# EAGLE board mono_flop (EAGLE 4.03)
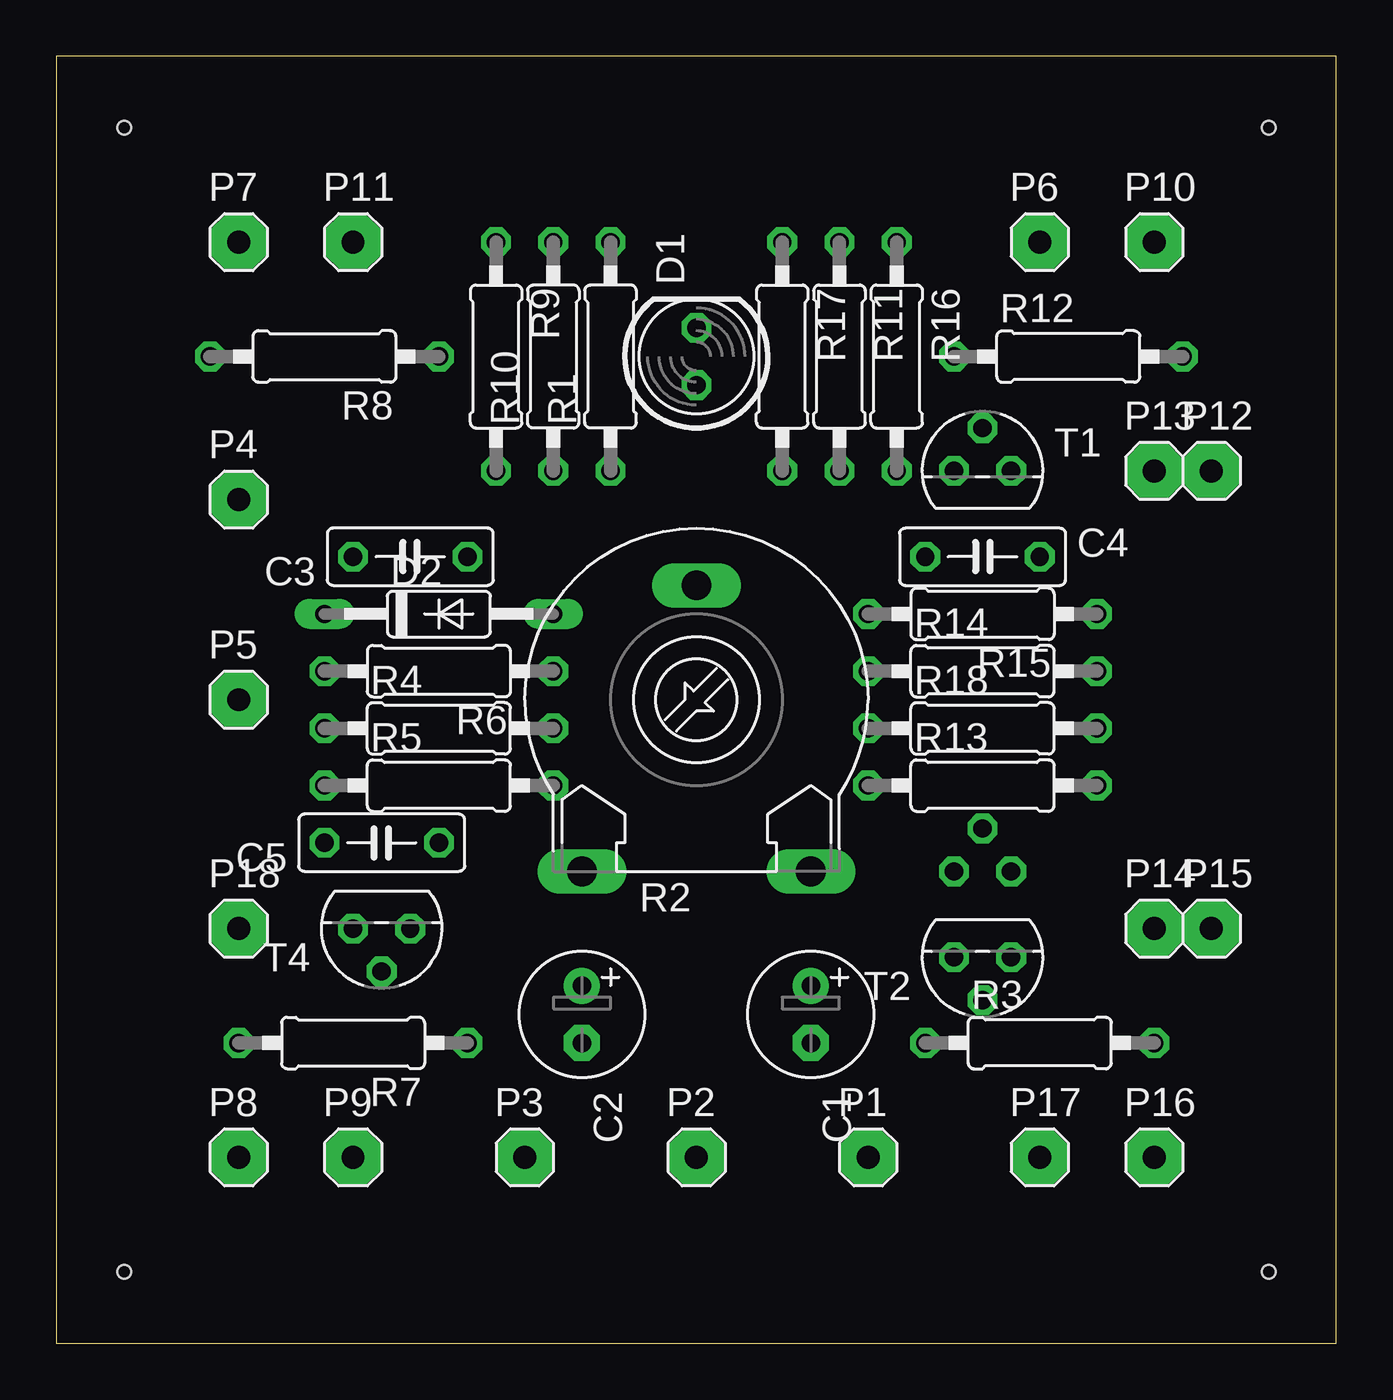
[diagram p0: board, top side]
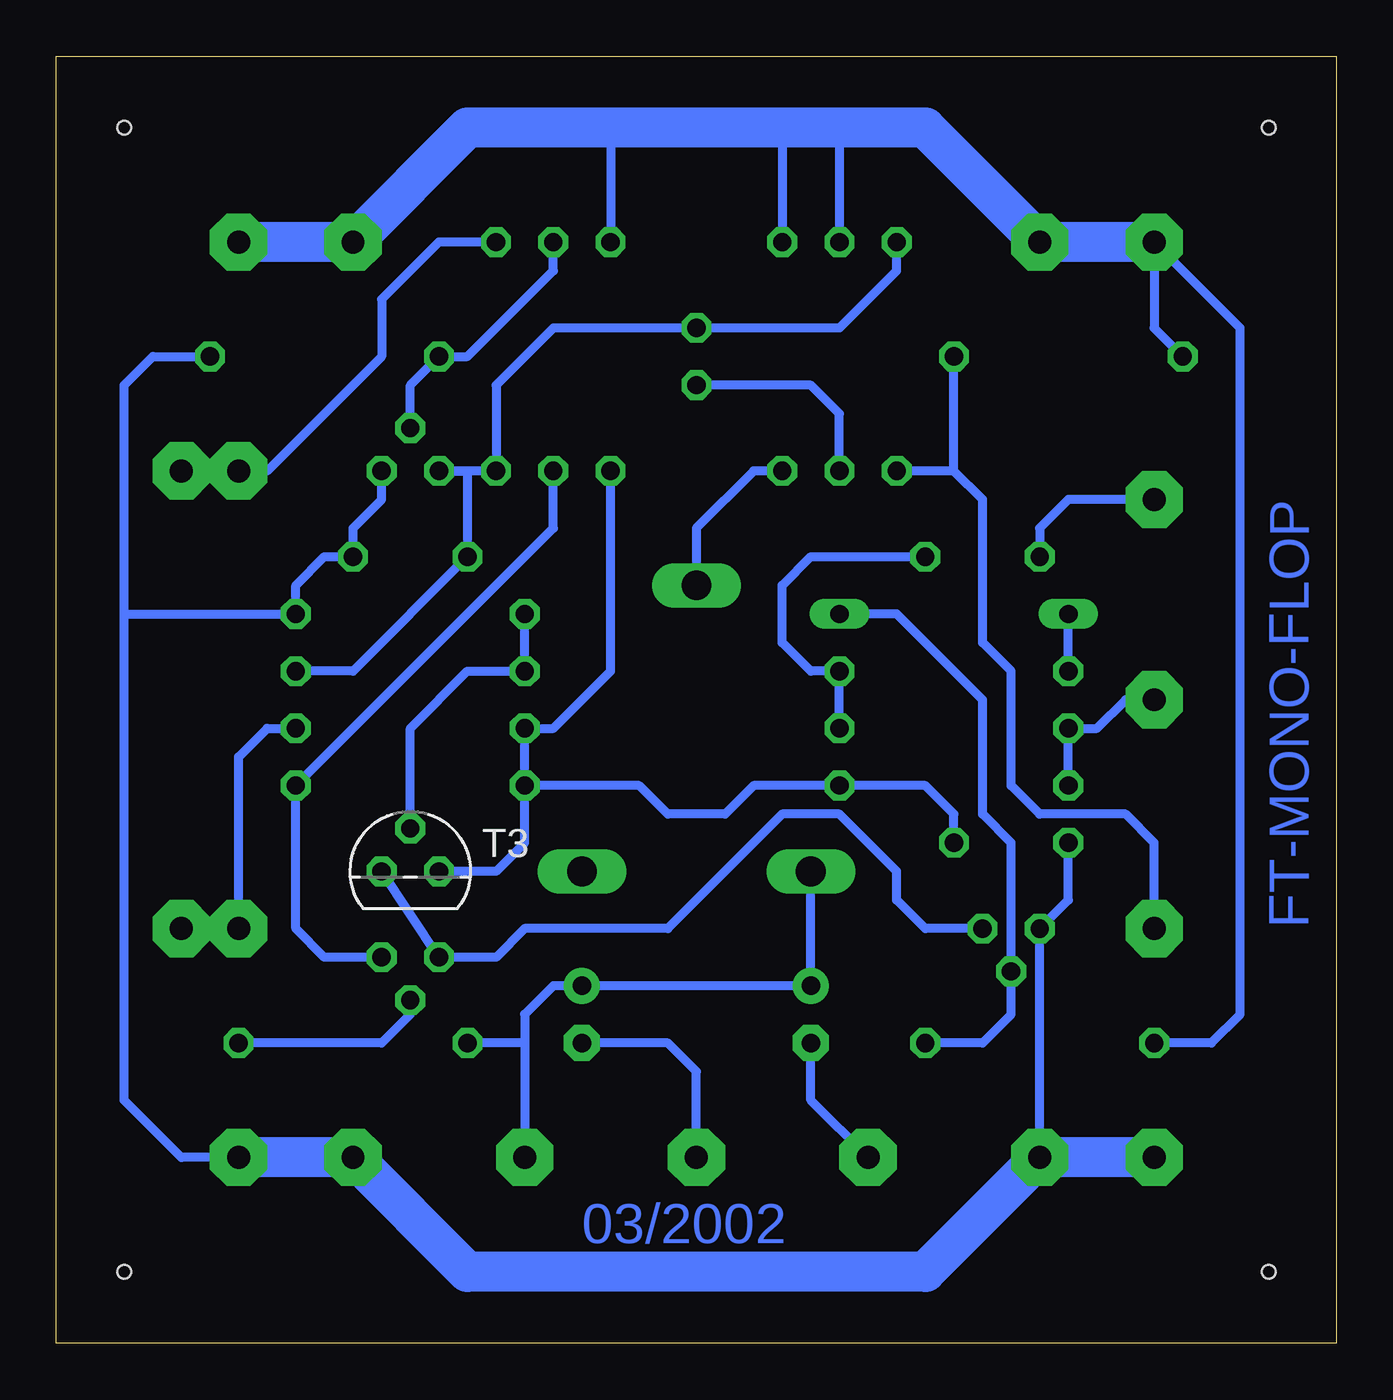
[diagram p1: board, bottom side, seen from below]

Size 56.82 x 57.14 mm. Coordinates in mm from the lower left corner, seen from the top.
Outline: 0,0 56.82,0 56.82,57.14 0,57.14 0,0
Copper layers used: Bottom
Holes 0.61 mm at 3.01,3.17 53.81,3.17 53.81,53.97 3.01,53.97

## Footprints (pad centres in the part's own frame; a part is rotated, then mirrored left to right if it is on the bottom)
E2,5-6 = drill 0.813 pad 1.6 round: + -1.27,0 | drill 0.813 pad 1.6 octagon: - 1.27,0
C050-025X075 = drill 0.813 octagon: 1 -2.54,0; 2 2.54,0
LED5MM = drill 0.813 octagon: A -1.27,0; K 1.27,0
DO35-10 = drill 0.813 long: A 5.08,0; C -5.08,0
1X01 = drill 1.016 pad 2.54 octagon: 1 0,0
0207/10 = drill 0.813 octagon: 1 -5.08,0; 2 5.08,0
LI15 = drill 1.321 long: 1 -5.08,-7.62; 2 0,5.08; 3 5.08,-7.62
TO92 = drill 0.813 octagon: 1 1.27,0; 2 0,1.905; 3 -1.27,0

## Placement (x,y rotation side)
C1  [E2,5-6]  33.49,14.6 270 top
C2  [E2,5-6]  23.33,14.6 270 top
C3  [C050-025X075]  15.71,34.92 180 top
C4  [C050-025X075]  41.11,34.92 0 top
C5  [C050-025X075]  14.44,22.22 180 top
D1  LED5MM  [LED5MM]  28.41,43.81 90 top
D2  1N4148  [DO35-10]  16.98,32.38 0 top
P1  EXT  [1X01]  36.03,8.25 0 top
P2  LANG  [1X01]  28.41,8.25 0 top
P3  KURZ  [1X01]  20.79,8.25 0 top
P4  SP  [1X01]  8.09,37.46 0 top
P5  SV  [1X01]  8.09,28.57 0 top
P6  +9V  [1X01]  43.65,48.89 0 top
P7  +9V  [1X01]  8.09,48.89 0 top
P8  GND  [1X01]  8.09,8.25 0 top
P9  GND  [1X01]  13.17,8.25 0 top
P10  +9V  [1X01]  48.73,48.89 0 top
P11  +9V  [1X01]  13.17,48.89 0 top
P12  Q  [1X01]  51.27,38.73 0 top
P13  Q  [1X01]  48.73,38.73 0 top
P14  -Q  [1X01]  48.73,18.41 0 top
P15  -Q  [1X01]  51.27,18.41 0 top
P16  GND  [1X01]  48.73,8.25 0 top
P17  GND  [1X01]  43.65,8.25 0 top
P18  zeit  [1X01]  8.09,18.41 0 top
R1  [0207/10]  24.6,43.81 90 top
R2  [LI15]  28.41,28.57 0 top
R3  [0207/10]  43.65,13.33 0 top
R4  [0207/10]  16.98,27.3 0 top
R5  [0207/10]  16.98,24.76 0 top
R6  [0207/10]  16.98,29.84 180 top
R7  [0207/10]  13.17,13.33 180 top
R8  [0207/10]  11.9,43.81 180 top
R9  [0207/10]  19.52,43.81 270 top
R10  [0207/10]  22.06,43.81 90 top
R11  [0207/10]  34.76,43.81 270 top
R12  [0207/10]  44.92,43.81 0 top
R13  [0207/10]  41.11,24.76 0 top
R14  [0207/10]  41.11,29.84 0 top
R15  [0207/10]  41.11,32.38 180 top
R16  [0207/10]  37.3,43.81 270 top
R17  [0207/10]  32.22,43.81 270 top
R18  [0207/10]  41.11,27.3 0 top
T1  BC238  [TO92]  41.11,38.73 0 top
T2  BC238  [TO92]  41.11,17.14 180 top
T3  BC238  [TO92]  41.11,20.95 0 bottom
T4  BC238  [TO92]  14.44,18.41 180 top

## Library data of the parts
C1-C5 R1 R3-R18 = rcl
D1 = led
D2 = diode
P1-P18 = pinhead
R2 = pot
T1-T4 = transistor-npn

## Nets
+9V: P6.1 P7.1 P10.1 P11.1 R1.2 R7.2 R8.2 R10.2 R17.1
GND: C4.2 C5.2 P8.1 P9.1 P16.1 P17.1 R12.2 R15.1 T1.1 T4.1
N$2: C3.2 P4.1
N$3: P5.1 R4.1 R5.1
N$5: R1.1 R2.2
N$6: C1.+ C2.+ P1.1 R2.1 R3.1
N$7: C1.- P2.1
N$8: C2.- P3.1
N$9: C3.1 R4.2 R6.1
N$12: R3.2 T2.2
N$13: D2.C R6.2
N$14: D2.A R7.1 T4.2
N$19: T2.1 T3.3 T4.3
N$20: R11.2 R13.2 T2.3
N$21: R11.1 R12.1 T1.2
N$24: P18.1 R8.1 R9.2
N$25: C4.1 D1.K R9.1 R14.2 R16.2 T1.3
N$27: D1.A R10.1
N$28: C5.1 R5.2 R13.1 R17.2 R18.1 T3.1
N$30: R14.1 R15.2 T3.2
N$33: P14.1 P15.1 R18.2
N$34: P12.1 P13.1 R16.1

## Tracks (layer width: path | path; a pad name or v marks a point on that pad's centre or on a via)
+9V
  Bottom 0.406: R8.2 8.09,45.08 P7.1 4.28,45.08 4.28,14.6 5.55,13.33 R7.2 | 32.22,53.97 R17.1 | 24.6,53.97 R1.2 | 22.06,53.97 R10.2
  Bottom 1.778: P7.1 P11.1 18.25,53.97 22.06,53.97 24.6,53.97 32.22,53.97 38.57,53.97 P6.1 P10.1
GND
  Bottom 0.406: R12.2 52.54,43.81 53.81,42.54 53.81,32.38 | T1.1 42.38,37.46 43.65,36.19 C4.2 44.92,34.92 46.19,33.65 R15.1 53.81,32.38 | P16.1 51.27,8.25 53.81,10.79 53.81,32.38 | P9.1 T4.1 11.9,19.68 C5.2
  Bottom 1.778: P8.1 P9.1 18.25,3.17 38.57,3.17 P17.1 P16.1
N$2
  Bottom 0.406: P4.1 11.9,37.46 13.17,36.19 C3.2
N$3
  Bottom 0.406: P5.1 9.36,28.57 10.63,27.3 R4.1 R5.1
N$5
  Bottom 0.406: R1.1 25.87,38.73 28.41,36.19 R2.2
N$6
  Bottom 0.406: 36.03,13.33 P1.1 | 36.03,13.33 R3.1 | 36.03,13.33 36.03,14.6 34.76,15.87 C1.+ C2.+ R2.1
N$7
  Bottom 0.406: P2.1 28.41,12.06 29.68,13.33 C1.-
N$8
  Bottom 0.406: P3.1 23.33,10.79 C2.-
N$9
  Bottom 0.406: R4.2 R6.1 23.33,29.84 24.6,31.11 24.6,33.65 23.33,34.92 C3.1
N$12
  Bottom 0.406: T2.2 41.11,14.6 42.38,13.33 R3.2
N$13
  Bottom 0.406: R6.2 D2.C
N$14
  Bottom 0.406: R7.1 15.71,13.33 14.44,14.6 T4.2 14.44,22.22 15.71,23.49 15.71,28.57 19.52,32.38 D2.A
N$19
  Bottom 0.406: T3.3 T2.1 37.3,17.14 36.03,18.41 29.68,18.41 24.6,23.49 22.06,23.49 19.52,20.95 19.52,19.68 18.25,18.41 T4.3
N$20
  Bottom 0.406: T2.3 44.92,17.14 46.19,18.41 R13.2 34.76,36.19 R11.2
N$21
  Bottom 0.406: T1.2 41.11,42.54 R12.1 38.57,43.81 34.76,47.62 R11.1
N$24
  Bottom 0.406: 16.98,38.73 R8.1 | 16.98,38.73 R9.2 | 16.98,38.73 15.71,37.46 15.71,31.11 14.44,29.84 14.44,24.76 13.17,23.49 9.36,23.49 8.09,22.22 P18.1
N$25
  Bottom 0.406: R14.2 43.65,29.84 C4.1 38.57,38.73 T1.3 R16.2 37.3,42.54 34.76,45.08 D1.K 22.06,45.08 19.52,47.62 R9.1
N$27
  Bottom 0.406: R10.1 22.06,41.27 23.33,42.54 D1.A
N$28
  Bottom 0.406: R13.1 R18.1 34.76,27.3 32.22,29.84 R17.2 | T3.1 37.3,20.95 36.03,22.22 R13.1 | C5.1 16.98,23.49 18.25,24.76 R5.2 25.87,24.76 27.14,23.49 29.68,23.49 30.95,24.76 R13.1
N$30
  Bottom 0.406: T3.2 41.11,27.3 38.57,29.84 R14.1 R15.2
N$33
  Bottom 0.406: R18.2 47.46,27.3 48.73,26.03 P14.1 P15.1
N$34
  Bottom 0.406: R16.1 39.84,48.89 42.38,46.35 42.38,43.81 47.46,38.73 P13.1 P12.1

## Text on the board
Bottom: FT-MONO-FLOP | 03/2002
